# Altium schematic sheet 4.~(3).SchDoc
size 420 x 297 mm
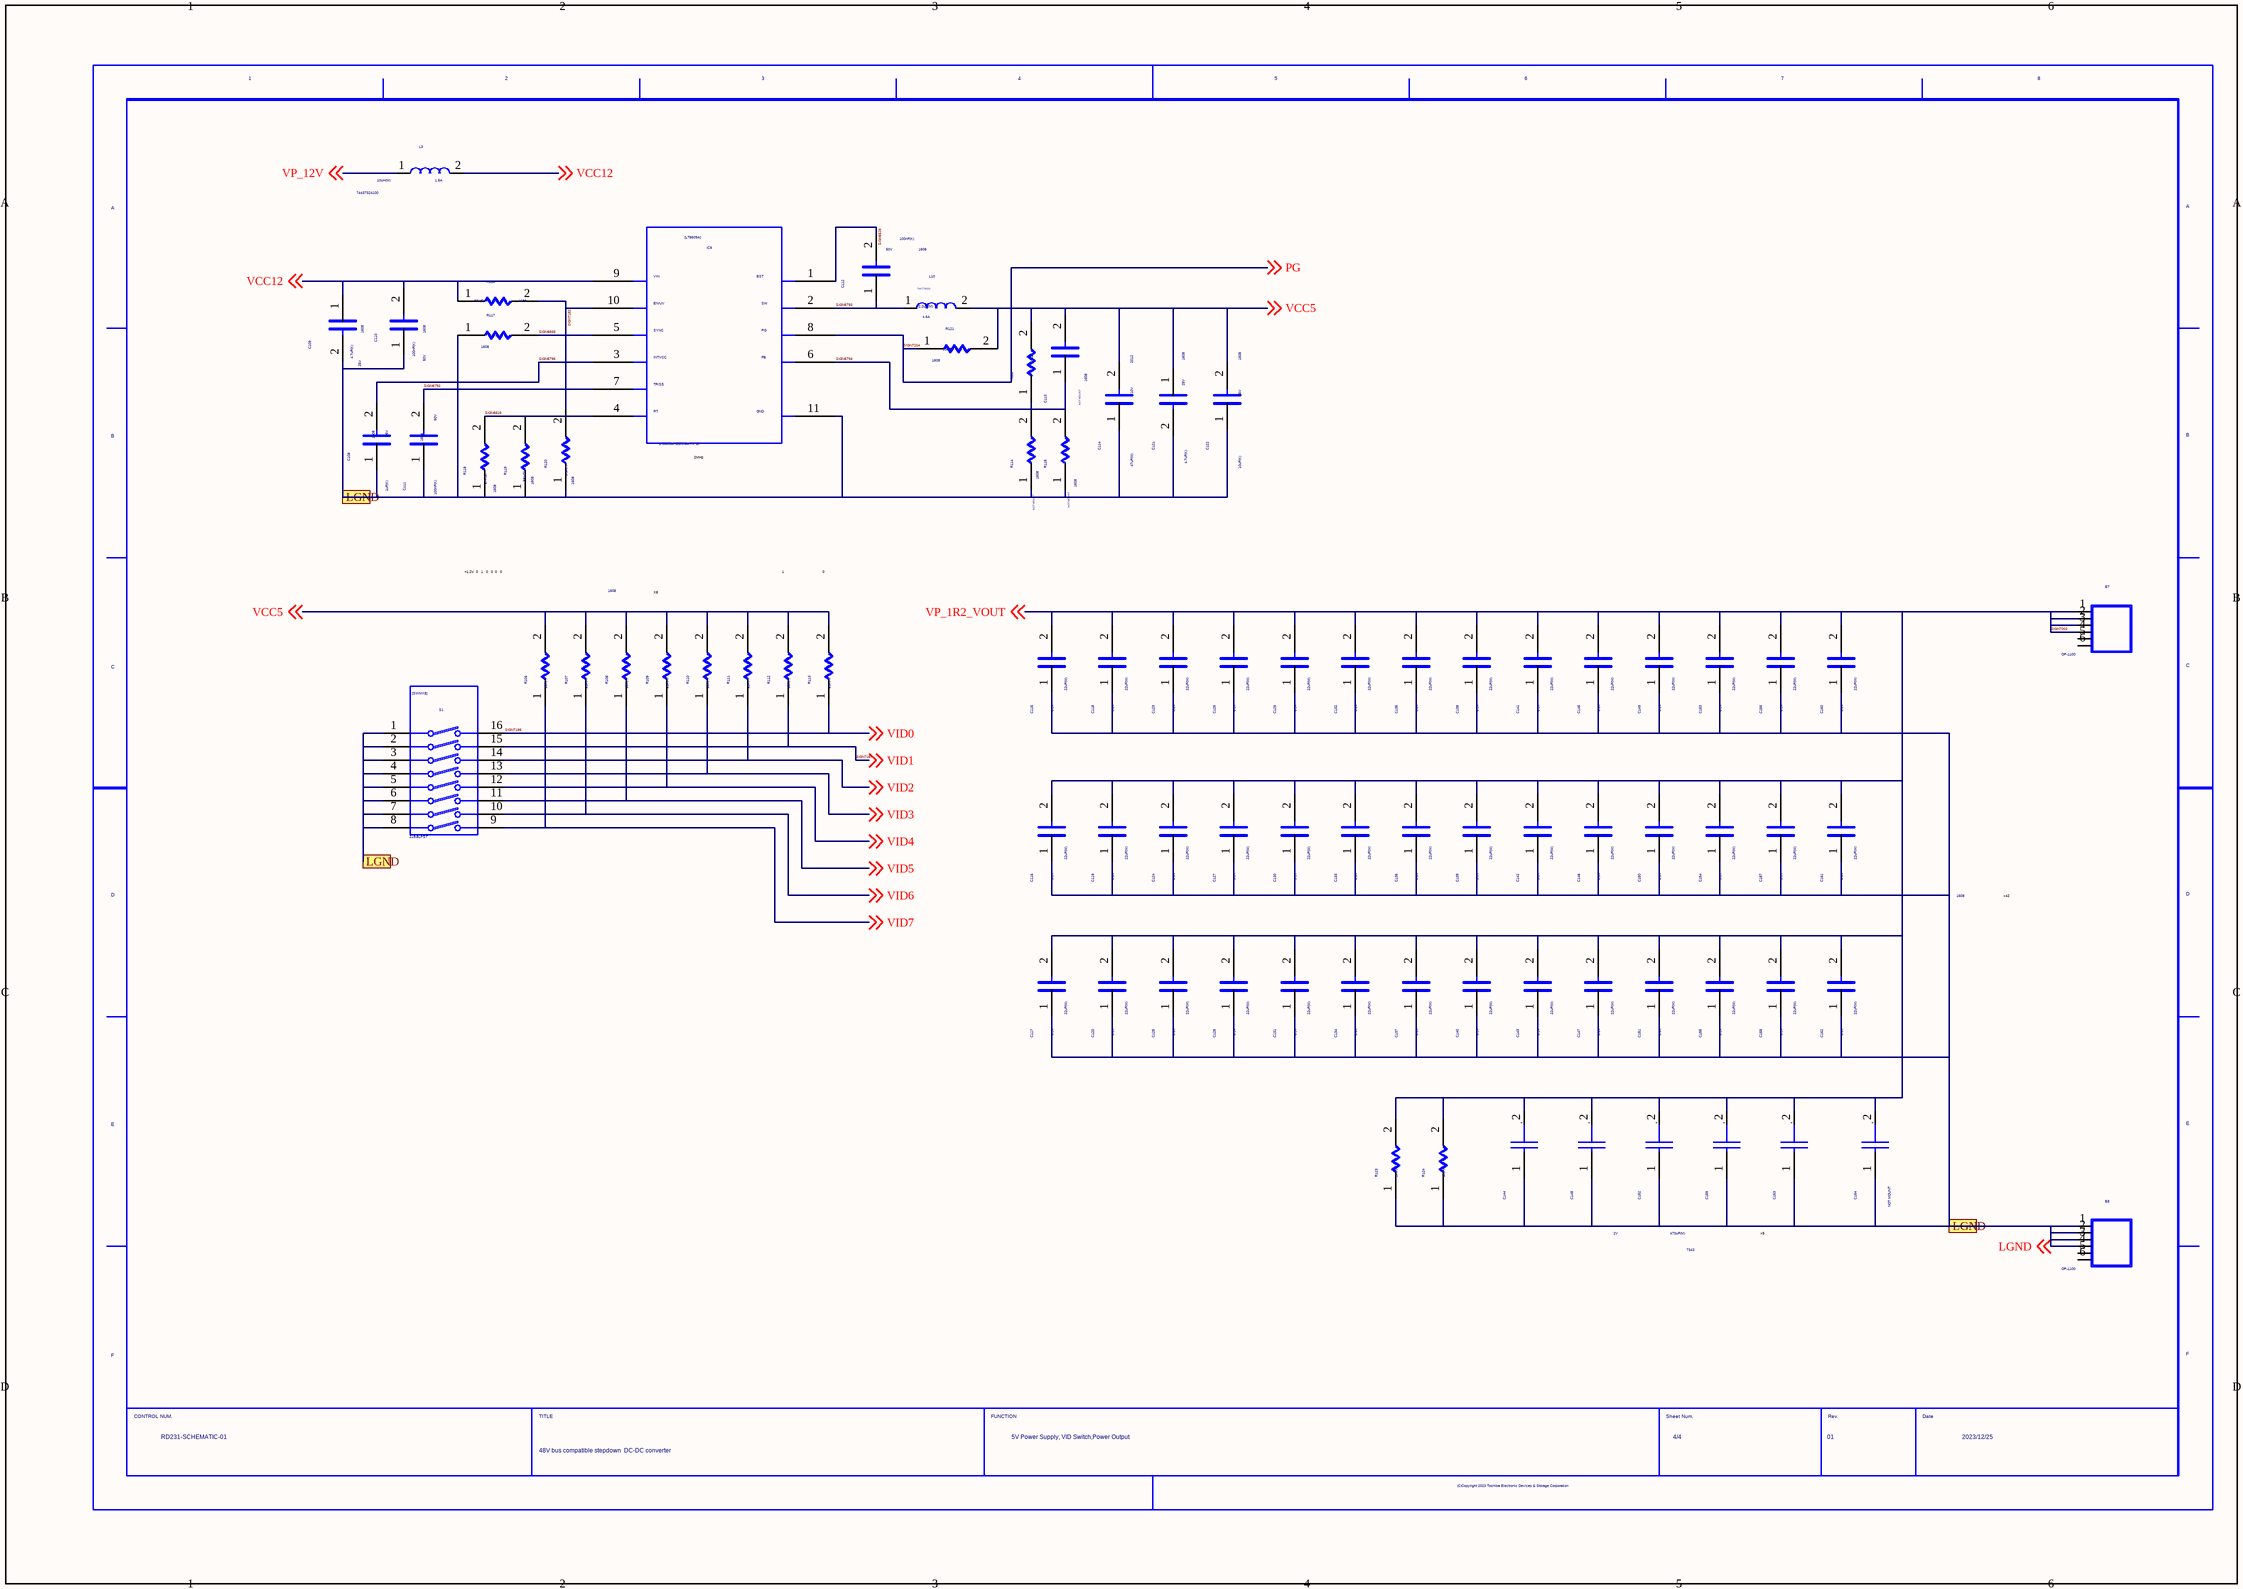
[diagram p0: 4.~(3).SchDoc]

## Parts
C108  VAL1: 1uF(K)  VAL2: 25V  SIZECODESMD: 1608  (hidden comment: C)
C109  VAL1: 4.7uF(K)  VAL2: 25V  SIZECODESMD: 1608  (hidden comment: C)
C110  VAL1: 100nF(K)  VAL2: 50V  SIZECODESMD: 1608  (hidden comment: C)
C111  VAL1: 100nF(K)  VAL2: 50V  SIZECODESMD: 1608  (hidden comment: C)
C112  VAL1: 100nF(K)  VAL2: 50V  SIZECODESMD: 1608  (hidden comment: C)
C113  NOTMOUNT: NOT MOUNT  SIZECODESMD: 1608  (hidden comment: C)
C114  VAL1: 47uF(M)  VAL2: 10V  SIZECODESMD: 2012  (hidden comment: C)
C115  VAL1: 22uF(M)  VAL2: 6.3V  (hidden comment: C)
C116  VAL1: 22uF(M)  VAL2: 6.3V  (hidden comment: C)
C117  VAL1: 22uF(M)  VAL2: 6.3V  (hidden comment: C)
C118  VAL1: 22uF(M)  VAL2: 6.3V  (hidden comment: C)
C119  VAL1: 22uF(M)  VAL2: 6.3V  (hidden comment: C)
C120  VAL1: 22uF(M)  VAL2: 6.3V  (hidden comment: C)
C121  VAL1: 4.7uF(K)  VAL2: 25V  SIZECODESMD: 1608  (hidden comment: C)
C122  VAL1: 10uF(K)  VAL2: 25V  SIZECODESMD: 1608  (hidden comment: C)
C123  VAL1: 22uF(M)  VAL2: 6.3V  (hidden comment: C)
C124  VAL1: 22uF(M)  VAL2: 6.3V  (hidden comment: C)
C125  VAL1: 22uF(M)  VAL2: 6.3V  (hidden comment: C)
C126  VAL1: 22uF(M)  VAL2: 6.3V  (hidden comment: C)
C127  VAL1: 22uF(M)  VAL2: 6.3V  (hidden comment: C)
C128  VAL1: 22uF(M)  VAL2: 6.3V  (hidden comment: C)
C129  VAL1: 22uF(M)  VAL2: 6.3V  (hidden comment: C)
C130  VAL1: 22uF(M)  VAL2: 6.3V  (hidden comment: C)
C131  VAL1: 22uF(M)  VAL2: 6.3V  (hidden comment: C)
C132  VAL1: 22uF(M)  VAL2: 6.3V  (hidden comment: C)
C133  VAL1: 22uF(M)  VAL2: 6.3V  (hidden comment: C)
C134  VAL1: 22uF(M)  VAL2: 6.3V  (hidden comment: C)
C135  VAL1: 22uF(M)  VAL2: 6.3V  (hidden comment: C)
C136  VAL1: 22uF(M)  VAL2: 6.3V  (hidden comment: C)
C137  VAL1: 22uF(M)  VAL2: 6.3V  (hidden comment: C)
C138  VAL1: 22uF(M)  VAL2: 6.3V  (hidden comment: C)
C139  VAL1: 22uF(M)  VAL2: 6.3V  (hidden comment: C)
C140  VAL1: 22uF(M)  VAL2: 6.3V  (hidden comment: C)
C141  VAL1: 22uF(M)  VAL2: 6.3V  (hidden comment: C)
C142  VAL1: 22uF(M)  VAL2: 6.3V  (hidden comment: C)
C143  VAL1: 22uF(M)  VAL2: 6.3V  (hidden comment: C)
C144  VAL1: 470uF(M)  VAL2: 2V  SIZECODESMD: 7343  (hidden comment: CP)
C145  VAL1: 22uF(M)  VAL2: 6.3V  (hidden comment: C)
C146  VAL1: 22uF(M)  VAL2: 6.3V  (hidden comment: C)
C147  VAL1: 22uF(M)  VAL2: 6.3V  (hidden comment: C)
C148  CP  (value not drawn)
C149  VAL1: 22uF(M)  VAL2: 6.3V  (hidden comment: C)
C150  VAL1: 22uF(M)  VAL2: 6.3V  (hidden comment: C)
C151  VAL1: 22uF(M)  VAL2: 6.3V  (hidden comment: C)
C152  CP  (value not drawn)
C153  VAL1: 22uF(M)  VAL2: 6.3V  (hidden comment: C)
C154  VAL1: 22uF(M)  VAL2: 6.3V  (hidden comment: C)
C155  VAL1: 22uF(M)  VAL2: 6.3V  (hidden comment: C)
C156  VAL1: 22uF(M)  VAL2: 6.3V  (hidden comment: C)
C157  VAL1: 22uF(M)  VAL2: 6.3V  (hidden comment: C)
C158  VAL1: 22uF(M)  VAL2: 6.3V  (hidden comment: C)
C159  CP  (value not drawn)
C160  VAL1: 22uF(M)  VAL2: 6.3V  (hidden comment: C)
C161  VAL1: 22uF(M)  VAL2: 6.3V  SIZECODESMD: 1608  (hidden comment: C)
C162  VAL1: 22uF(M)  VAL2: 6.3V  (hidden comment: C)
C163  CP  (value not drawn)
C164  NOTMOUNT: NOT MOUNT  (hidden comment: CP)
E7  VAL3: OP-1100  (hidden comment: EB1)
E8  VAL3: OP-1100  (hidden comment: EB1)
IC9  COMP: LT8609AHDDM-5#TRPBF  (hidden comment: LT8609A)
L3  VAL1: 10uH(M)  VAL2: 1.5A  VAL3: 74437324100  (hidden comment: L)
L10  COMP: 744774022  VAL1: 2.2uH(M)  VAL2: 4.6A  (hidden comment: L)
R106  VAL1: 10k(F)  SIZECODESMD: 1608  (hidden comment: R)
R107  VAL1: 10k(F)  (hidden comment: R)
R108  VAL1: 10k(F)  (hidden comment: R)
R109  VAL1: 10k(F)  (hidden comment: R)
R110  VAL1: 10k(F)  (hidden comment: R)
R111  VAL1: 10k(F)  (hidden comment: R)
R112  VAL1: 10k(F)  (hidden comment: R)
R113  VAL1: 10k(F)  (hidden comment: R)
R114  NOTMOUNT: NOT MOUNT  SIZECODESMD: 1608  (hidden comment: R)
R115  NOTMOUNT: NOT MOUNT  SIZECODESMD: 1608  (hidden comment: R)
R116  VAL1: 33k(F)  SIZECODESMD: 1608  (hidden comment: R)
R117  VAL1: 0  SIZECODESMD: 1608  (hidden comment: R)
R118  VAL1: 27k(D)  SIZECODESMD: 1608  (hidden comment: R)
R119  VAL1: 56k(D)  SIZECODESMD: 1608  (hidden comment: R)
R120  VAL1: 3.9k(F)  SIZECODESMD: 1608  (hidden comment: R)
R121  VAL1: 10k(F)  SIZECODESMD: 1608  (hidden comment: R)
R122  VAL1: 0  SIZECODESMD: 1608  (hidden comment: R)
R123  VAL1: 1k(F)  (hidden comment: R)
R124  VAL1: 1k(F)  (hidden comment: R)
S1  COMP: 219-8LPST  (hidden comment: SWMX8)
U?  DATE: 2023/12/25  FUNCTION: 5V Power Supply, VID Switch,Power Output  DRAWINGNUMBER: RD231-SCHEMATIC-01  SHEETNUMBER: 4/4  REVISION: 01  TITLE: 48V bus compatible stepdown / DC-DC converter  (hidden comment: WAKU_DEF100)

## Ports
LGND

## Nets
LGND: C108.1 C109.2 C110.1 C111.1 C114.1 C115.1 C116.1 C117.1 C118.1 C119.1 C120.1 C121.2 C122.1 C123.1 C124.1 C125.1 C126.1 C127.1 C128.1 C129.1 C130.1 C131.1 C132.1 C133.1 C134.1 C135.1 C136.1 C137.1 C138.1 C139.1 C140.1 C141.1 C142.1 C143.1 C144.1 C145.1 C146.1 C147.1 C148.1 C149.1 C150.1 C151.1 C152.1 C153.1 C154.1 C155.1 C156.1 C157.1 C158.1 C159.1 C160.1 C161.1 C162.1 C163.1 C164.1 E8.1 E8.2 E8.3 E8.4 IC9.11 R114.1 R115.1 R117.1 R118.1 R119.1 R120.1 R123.1 R124.1 S1.1 S1.2 S1.3 S1.4 S1.5 S1.6 S1.7 S1.8 ; off-sheet LGND, port LGND
SIGN6792: C111.2 IC9.7
SIGN6793: C112.1 IC9.2 L10.1
SIGN6794: C113.1 IC9.6 R114.2 R115.2 R122.1
SIGN6796: C108.2 IC9.3
SIGN6815: IC9.4 R118.2 R119.2
SIGN6828: C112.2 IC9.1
SIGN6838: IC9.5 R117.2
SIGN7002: C115.2 C116.2 C117.2 C118.2 C119.2 C120.2 C123.2 C124.2 C125.2 C126.2 C127.2 C128.2 C129.2 C130.2 C131.2 C132.2 C133.2 C134.2 C135.2 C136.2 C137.2 C138.2 C139.2 C140.2 C141.2 C142.2 C143.2 C144.2 C145.2 C146.2 C147.2 C148.2 C149.2 C150.2 C151.2 C152.2 C153.2 C154.2 C155.2 C156.2 C157.2 C158.2 C159.2 C160.2 C161.2 C162.2 C163.2 C164.2 E7.1 E7.2 E7.3 E7.4 R123.2 R124.2 ; off-sheet VP_1R2_VOUT  [also labelled VP_1R2_VOUT]
SIGN7182: IC9.10 R116.2 R120.2
SIGN7186: R113.1 S1.16 ; off-sheet VID0  [also labelled VID0]
SIGN7187: R112.1 S1.15 ; off-sheet VID1  [also labelled VID1]
SIGN7204: IC9.8 R121.1 ; off-sheet PG  [also labelled PG]
VCC5: C113.2 C114.2 C121.1 C122.2 L10.2 R106.2 R107.2 R108.2 R109.2 R110.2 R111.2 R112.2 R113.2 R121.2 R122.2 ; off-sheet VCC5
VCC12: C109.1 C110.2 IC9.9 L3.2 R116.1 ; off-sheet VCC12
VID2: R111.1 S1.14 ; off-sheet VID2
VID3: R110.1 S1.13 ; off-sheet VID3
VID4: R109.1 S1.12 ; off-sheet VID4
VID5: R108.1 S1.11 ; off-sheet VID5
VID6: R107.1 S1.10 ; off-sheet VID6
VID7: R106.1 S1.9 ; off-sheet VID7
VP_12V: L3.1 ; off-sheet VP_12V

Not connected (* = marked no-connect by the designer): E7 5 6; E8 5 6

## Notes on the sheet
- (near IC9) 2MHz
- +1.2V  0   1   0   0  0   0
- X8
- 1
- 0
- x42
- x5

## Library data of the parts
C108 = C: FNPARTSNAMEG: CHIP CERAMIC CAPACITOR (1608); OriginalSymbolOrigin: (2540,7620); USEWITHSCHEMA: YES; FUNCN: G36030011433; MFPACKAGEMETHOP: S; COMPONENTNAME: G36030011433_package; GCOUNT: 1; FNCLASSCODEG: P03-03; MFMOUNTSYMBOLP: 80; MFFORMINGDIVP: KC; MFSOLDERINGPROP: .; PCODE: P03039992230
C109 = C: FNPARTSNAMEG: CHIP CERAMIC CAPACITOR (1608); OriginalSymbolOrigin: (2540,7620); FNCLASSCODEG: P03-03; PCODE: P03B000000MS; USEWITHSCHEMA: YES; MFMOUNTSYMBOLP: 80; FUNCN: GDM030000053; MFFORMINGDIVP: KC; MFPACKAGEMETHOP: S; MFSOLDERINGPROP: .; COMPONENTNAME: GDM030000053_package; GCOUNT: 1
C110 C112 = C: FNPARTSNAMEG: CHIP CERAMIC CAPACITOR (1608); OriginalSymbolOrigin: (2540,7620); USEWITHSCHEMA: YES; FUNCN: G36030104036; MFPACKAGEMETHOP: S; COMPONENTNAME: G36030104036_package; GCOUNT: 1; FNCLASSCODEG: P03-03; PCODE: P03039A6F224; MFMOUNTSYMBOLP: 80; MFFORMINGDIVP: KC; MFSOLDERINGPROP: .
C111 = C: PARTCOMMENT: 代表セル<KC0008> がフットプリントに登録されていません。; FNPARTSNAMEG: CHIP CERAMIC CAPACITOR (1608); OriginalSymbolOrigin: (2540,7620); USEWITHSCHEMA: YES; FUNCN: GDM030001137; MFPACKAGEMETHOP: S; COMPONENTNAME: GDM030001137_package; GCOUNT: 1; FNCLASSCODEG: P03-03; PCODE: P03B000001KW; MFMOUNTSYMBOLP: 80; MFFORMINGDIVP: KC; MFSOLDERINGPROP: .
C113 = C: FNPARTSNAMEG: CHIP CERAMIC CAPACITOR (1608); OriginalSymbolOrigin: (2540,7620); USEWITHSCHEMA: YES; FUNCN: G36030011013; MFPACKAGEMETHOP: S; COMPONENTNAME: G36030011013_package; GCOUNT: 1; FNCLASSCODEG: P03-03; PCODE: P03039185229; MFMOUNTSYMBOLP: 80; MFFORMINGDIVP: KC; MFSOLDERINGPROP: .; TOLERANCE: D
C114 = C: FNPARTSNAMEG: CHIP CERAMIC CAPACITOR (2012); OriginalSymbolOrigin: (2540,7620); USEWITHSCHEMA: YES; FUNCN: GDM030000019; MFPACKAGEMETHOP: S; COMPONENTNAME: GDM030000019_package; GCOUNT: 1; FNCLASSCODEG: P03-03; PCODE: P03B0000004U; MFMOUNTSYMBOLP: 80; MFFORMINGDIVP: KC; MFSOLDERINGPROP: .
C115-C120 C123-C143 C145-C147 C149-C151 C153-C158 C160 C162 = C: FNPARTSNAMEG: CHIP CERAMIC CAPACITOR (1608); OriginalSymbolOrigin: (2540,7620); USEWITHSCHEMA: YES; FUNCN: GDM030000053; MFPACKAGEMETHOP: S; COMPONENTNAME: GDM030000053_package; GCOUNT: 1; FNCLASSCODEG: P03-03; MFMOUNTSYMBOLP: 80; SIZECODESMD: 1608; MFFORMINGDIVP: KC; MFSOLDERINGPROP: .; PCODE: P03B000000MS
C121 = C: FNPARTSNAMEG: CHIP CERAMIC CAPACITOR (1608); OriginalSymbolOrigin: (2540,7620); FNCLASSCODEG: P03-03; PCODE: P03039992230; USEWITHSCHEMA: YES; MFMOUNTSYMBOLP: 80; FUNCN: G36030011433; MFFORMINGDIVP: KC; MFPACKAGEMETHOP: S; MFSOLDERINGPROP: .; COMPONENTNAME: G36030011433_package; GCOUNT: 1
C122 C161 = C: FNPARTSNAMEG: CHIP CERAMIC CAPACITOR (1608); OriginalSymbolOrigin: (2540,7620); USEWITHSCHEMA: YES; FUNCN: GDM030000053; MFPACKAGEMETHOP: S; COMPONENTNAME: GDM030000053_package; GCOUNT: 1; FNCLASSCODEG: P03-03; MFMOUNTSYMBOLP: 80; MFFORMINGDIVP: KC; MFSOLDERINGPROP: .; PCODE: P03B000000MS
C144 = CP: FNPARTSCODEG: C; FNPARTSNAMEG: POSCAP (TPB); SAVEAREA0: -1450,-153,20294,13055; SAVECOUNT: 52; TIME: 15:02:55; UPDATEUSER: fukuda-y; UPDATETIME: 16:13:42; OriginalSymbolOrigin: (2540,10160); USEWITHSCHEMA: YES; FUNCN: G36030149044; GCOUNT: 1; COMPONENTNAME: G36030149044_package; FNCLASSCODEG: P03-02; PCODE: P03217004212; MFMOUNTSYMBOLP: 80; MFFORMINGDIVP: KD; MFPACKAGEMETHOP: S; MFSOLDERINGPROP: .
C148 C152 C159 C163 = CP: FNPARTSCODEG: C; FNPARTSNAMEG: POSCAP (TPB); SAVEAREA0: -1450,-153,20294,13055; SAVECOUNT: 52; TIME: 15:02:55; UPDATEUSER: fukuda-y; UPDATETIME: 16:13:42; OriginalSymbolOrigin: (2540,10160); USEWITHSCHEMA: YES; FUNCN: G36030149044; GCOUNT: 1; COMPONENTNAME: G36030149044_package; VAL1: 470uF(M); VAL2: 2V; FNCLASSCODEG: P03-02; PCODE: P03217004212; MFMOUNTSYMBOLP: 80; SIZECODESMD: 7343; MFFORMINGDIVP: KD; MFPACKAGEMETHOP: S; MFSOLDERINGPROP: .
C164 = CP: FNPARTSCODEG: C; FNPARTSNAMEG: POSCAP (TPB); SAVEAREA0: -1450,-153,20294,13055; SAVECOUNT: 52; TIME: 15:02:55; UPDATEUSER: fukuda-y; UPDATETIME: 16:13:42; OriginalSymbolOrigin: (2540,10160); USEWITHSCHEMA: YES; FUNCN: G36030149044; GCOUNT: 1; COMPONENTNAME: G36030149044_package; FNCLASSCODEG: P03-02; PCODE: P03217004212; MFMOUNTSYMBOLP: 80; SIZECODESMD: 7343; MFFORMINGDIVP: KD; MFPACKAGEMETHOP: S; MFSOLDERINGPROP: .
E7 E8 = EB1: SAVEAREA0: -19495,-9575,29572,17273; TIME: 17:33:04; UPDATEUSER: sptcae13; UPDATETIME: 17:37:19; SAVECOUNT: 4; OriginalSymbolOrigin: (0,10160)
IC9 = LT8609A: TIME: 17:49:40; UPDATEUSER: q91866sr; UPDATETIME: 14:18:47; SAVECOUNT: 44; SAVEAREA0: -19850,-898,65678,46399; OriginalSymbolOrigin: (7620,43180); USEWITHSCHEMA: YES; GCOUNT: 1; OUMEMAKER: Analog Devices; COMPONENTNAME: pinass:LT8609A_func:LT8609A
L3 L10 = L: OriginalSymbolOrigin: (2540,5080); USEWITHSCHEMA: YES; OUMEMAKER: Wurth Elektronik; COMPONENTNAME: L.L; GCOUNT: 1
R106 = R: FNPARTSNAMEG: CHIP RESISTOR (1608); OriginalSymbolOrigin: (5080,5080); FNCLASSCODEG: P01-08; PCODE: P01042049A26; USEWITHSCHEMA: YES; VAL2: 100mW; NUMBEROFELEMENT: 0; MFMOUNTSYMBOLP: 80; COMP: G36010027034; MFFORMINGDIVP: KC; MFPACKAGEMETHOP: S; MFSOLDERINGPROP: .; TOLERANCE: F; COMPONENTNAME: G36010027034_package
R107-R113 = R: FNPARTSNAMEG: CHIP RESISTOR (1608); OriginalSymbolOrigin: (5080,5080); FNCLASSCODEG: P01-08; PCODE: P01042049A26; USEWITHSCHEMA: YES; VAL2: 100mW; NUMBEROFELEMENT: 0; MFMOUNTSYMBOLP: 80; COMP: G36010027034; MFFORMINGDIVP: KC; MFPACKAGEMETHOP: S; MFSOLDERINGPROP: .; TOLERANCE: F; COMPONENTNAME: G36010027034_package; SIZECODESMD: 1608
R114 = R: FNPARTSNAMEG: CHIP RESISTOR (1608); OriginalSymbolOrigin: (5080,5080); FNCLASSCODEG: P01-08; PCODE: P01042409226; USEWITHSCHEMA: YES; NUMBEROFELEMENT: 0; MFMOUNTSYMBOLP: 80; COMP: G36010104216; MFFORMINGDIVP: KC; MFPACKAGEMETHOP: S; MFSOLDERINGPROP: .; TOLERANCE: F; COMPONENTNAME: G36010104216_package
R115 = R: FNPARTSNAMEG: CHIP RESISTOR (1608); OriginalSymbolOrigin: (5080,5080); FNCLASSCODEG: P01-08; PCODE: P01042237423; USEWITHSCHEMA: YES; NUMBEROFELEMENT: 0; MFMOUNTSYMBOLP: 80; COMP: G36010103110; MFFORMINGDIVP: KC; MFPACKAGEMETHOP: S; MFSOLDERINGPROP: .; TOLERANCE: J; COMPONENTNAME: G36010103110_package
R116 = R: FNPARTSNAMEG: CHIP RESISTOR (1608); OriginalSymbolOrigin: (5080,5080); FNCLASSCODEG: P01-08; USEWITHSCHEMA: YES; VAL2: 100mW; COMP: G36010027171; COMPONENTNAME: G36010027171_package; GCOUNT: 1; PCODE: P01042295621; NUMBEROFELEMENT: 0; MFMOUNTSYMBOLP: 80; MFFORMINGDIVP: KC; MFPACKAGEMETHOP: S; MFSOLDERINGPROP: .; TOLERANCE: F
R117 R122 = R: PARTCOMMENT: 代表セル<KC0008> がフットプリントに登録されていません。; FNPARTSNAMEG: CHIP JUMPER 1608TYPE; OriginalSymbolOrigin: (5080,5080); FNCLASSCODEG: P01-08; USEWITHSCHEMA: YES; COMP: K0100346; COMPONENTNAME: K0100346_package; GCOUNT: 1
R118 = R: FNPARTSNAMEG: CHIP RESISTOR (1608); OriginalSymbolOrigin: (5080,5080); FNCLASSCODEG: P01-08; PCODE: P01117063117; USEWITHSCHEMA: YES; VAL2: 62.5mW; NUMBEROFELEMENT: 0; MFMOUNTSYMBOLP: 80; COMP: G36010129592; MFFORMINGDIVP: KC; MFPACKAGEMETHOP: S; MFSOLDERINGPROP: .; COMPONENTNAME: G36010129592_package; GCOUNT: 1
R119 = R: FNPARTSNAMEG: CHIP RESISTOR (1608); OriginalSymbolOrigin: (5080,5080); FNCLASSCODEG: P01-08; PCODE: P01042600623; USEWITHSCHEMA: YES; VAL2: 62.5mW; NUMBEROFELEMENT: 0; MFMOUNTSYMBOLP: 80; COMP: G36010014676; MFFORMINGDIVP: KC; MFPACKAGEMETHOP: S; MFSOLDERINGPROP: .; COMPONENTNAME: G36010014676_package; GCOUNT: 1
R120 = R: FNPARTSNAMEG: CHIP RESISTOR (1608); OriginalSymbolOrigin: (5080,5080); FNCLASSCODEG: P01-08; PCODE: P01042262227; USEWITHSCHEMA: YES; VAL2: 100mW; NUMBEROFELEMENT: 0; MFMOUNTSYMBOLP: 80; COMP: G36010104254; MFFORMINGDIVP: KC; MFPACKAGEMETHOP: S; MFSOLDERINGPROP: .; COMPONENTNAME: G36010104254_package; GCOUNT: 1; TOLERANCE: F
R121 = R: FNPARTSNAMEG: CHIP RESISTOR (1608); OriginalSymbolOrigin: (5080,5080); FNCLASSCODEG: P01-08; USEWITHSCHEMA: YES; VAL2: 100mW; COMP: G36010027034; COMPONENTNAME: G36010027034_package; GCOUNT: 1; PCODE: P01042049A26; NUMBEROFELEMENT: 0; MFMOUNTSYMBOLP: 80; MFFORMINGDIVP: KC; MFPACKAGEMETHOP: S; MFSOLDERINGPROP: .; TOLERANCE: F
R123 R124 = R: FNPARTSNAMEG: CHIP RESISTOR (1608); OriginalSymbolOrigin: (5080,5080); FNCLASSCODEG: P01-08; PCODE: P01042521225; USEWITHSCHEMA: YES; VAL2: 100mW; NUMBEROFELEMENT: 0; MFMOUNTSYMBOLP: 80; COMP: G36010027324; MFFORMINGDIVP: KC; MFPACKAGEMETHOP: S; MFSOLDERINGPROP: .; TOLERANCE: F; COMPONENTNAME: G36010027324_package; GCOUNT: 1; SIZECODESMD: 1608
S1 = SWMX8: OriginalSymbolOrigin: (5080,30480); USEWITHSCHEMA: YES; OUMEMAKER: CTS; COMPONENTNAME: SWMX8.SWMX8; GCOUNT: 1
U? = WAKU_DEF100: PLOTTIME: HH:MM; SAVEAREA0: 330961,54,387907,31546; TIME: 19:23:07; UPDATEUSER: sptcae13; UPDATETIME: 17:47:42; SAVECOUNT: 8; OriginalSymbolOrigin: (10160,284480)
